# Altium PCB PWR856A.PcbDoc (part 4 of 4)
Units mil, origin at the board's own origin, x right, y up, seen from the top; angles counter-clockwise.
Board outline 4000 x 4000 mil, 8 copper layers (Top Layer, Signal Layer 1, Signal Layer 2, Signal Layer 3, Signal Layer 4, Signal Layer 5, Signal Layer 6, Bottom Layer), stack 60.4 mil thick; 246 components, 78 nets, 563 pads, 817 vias.
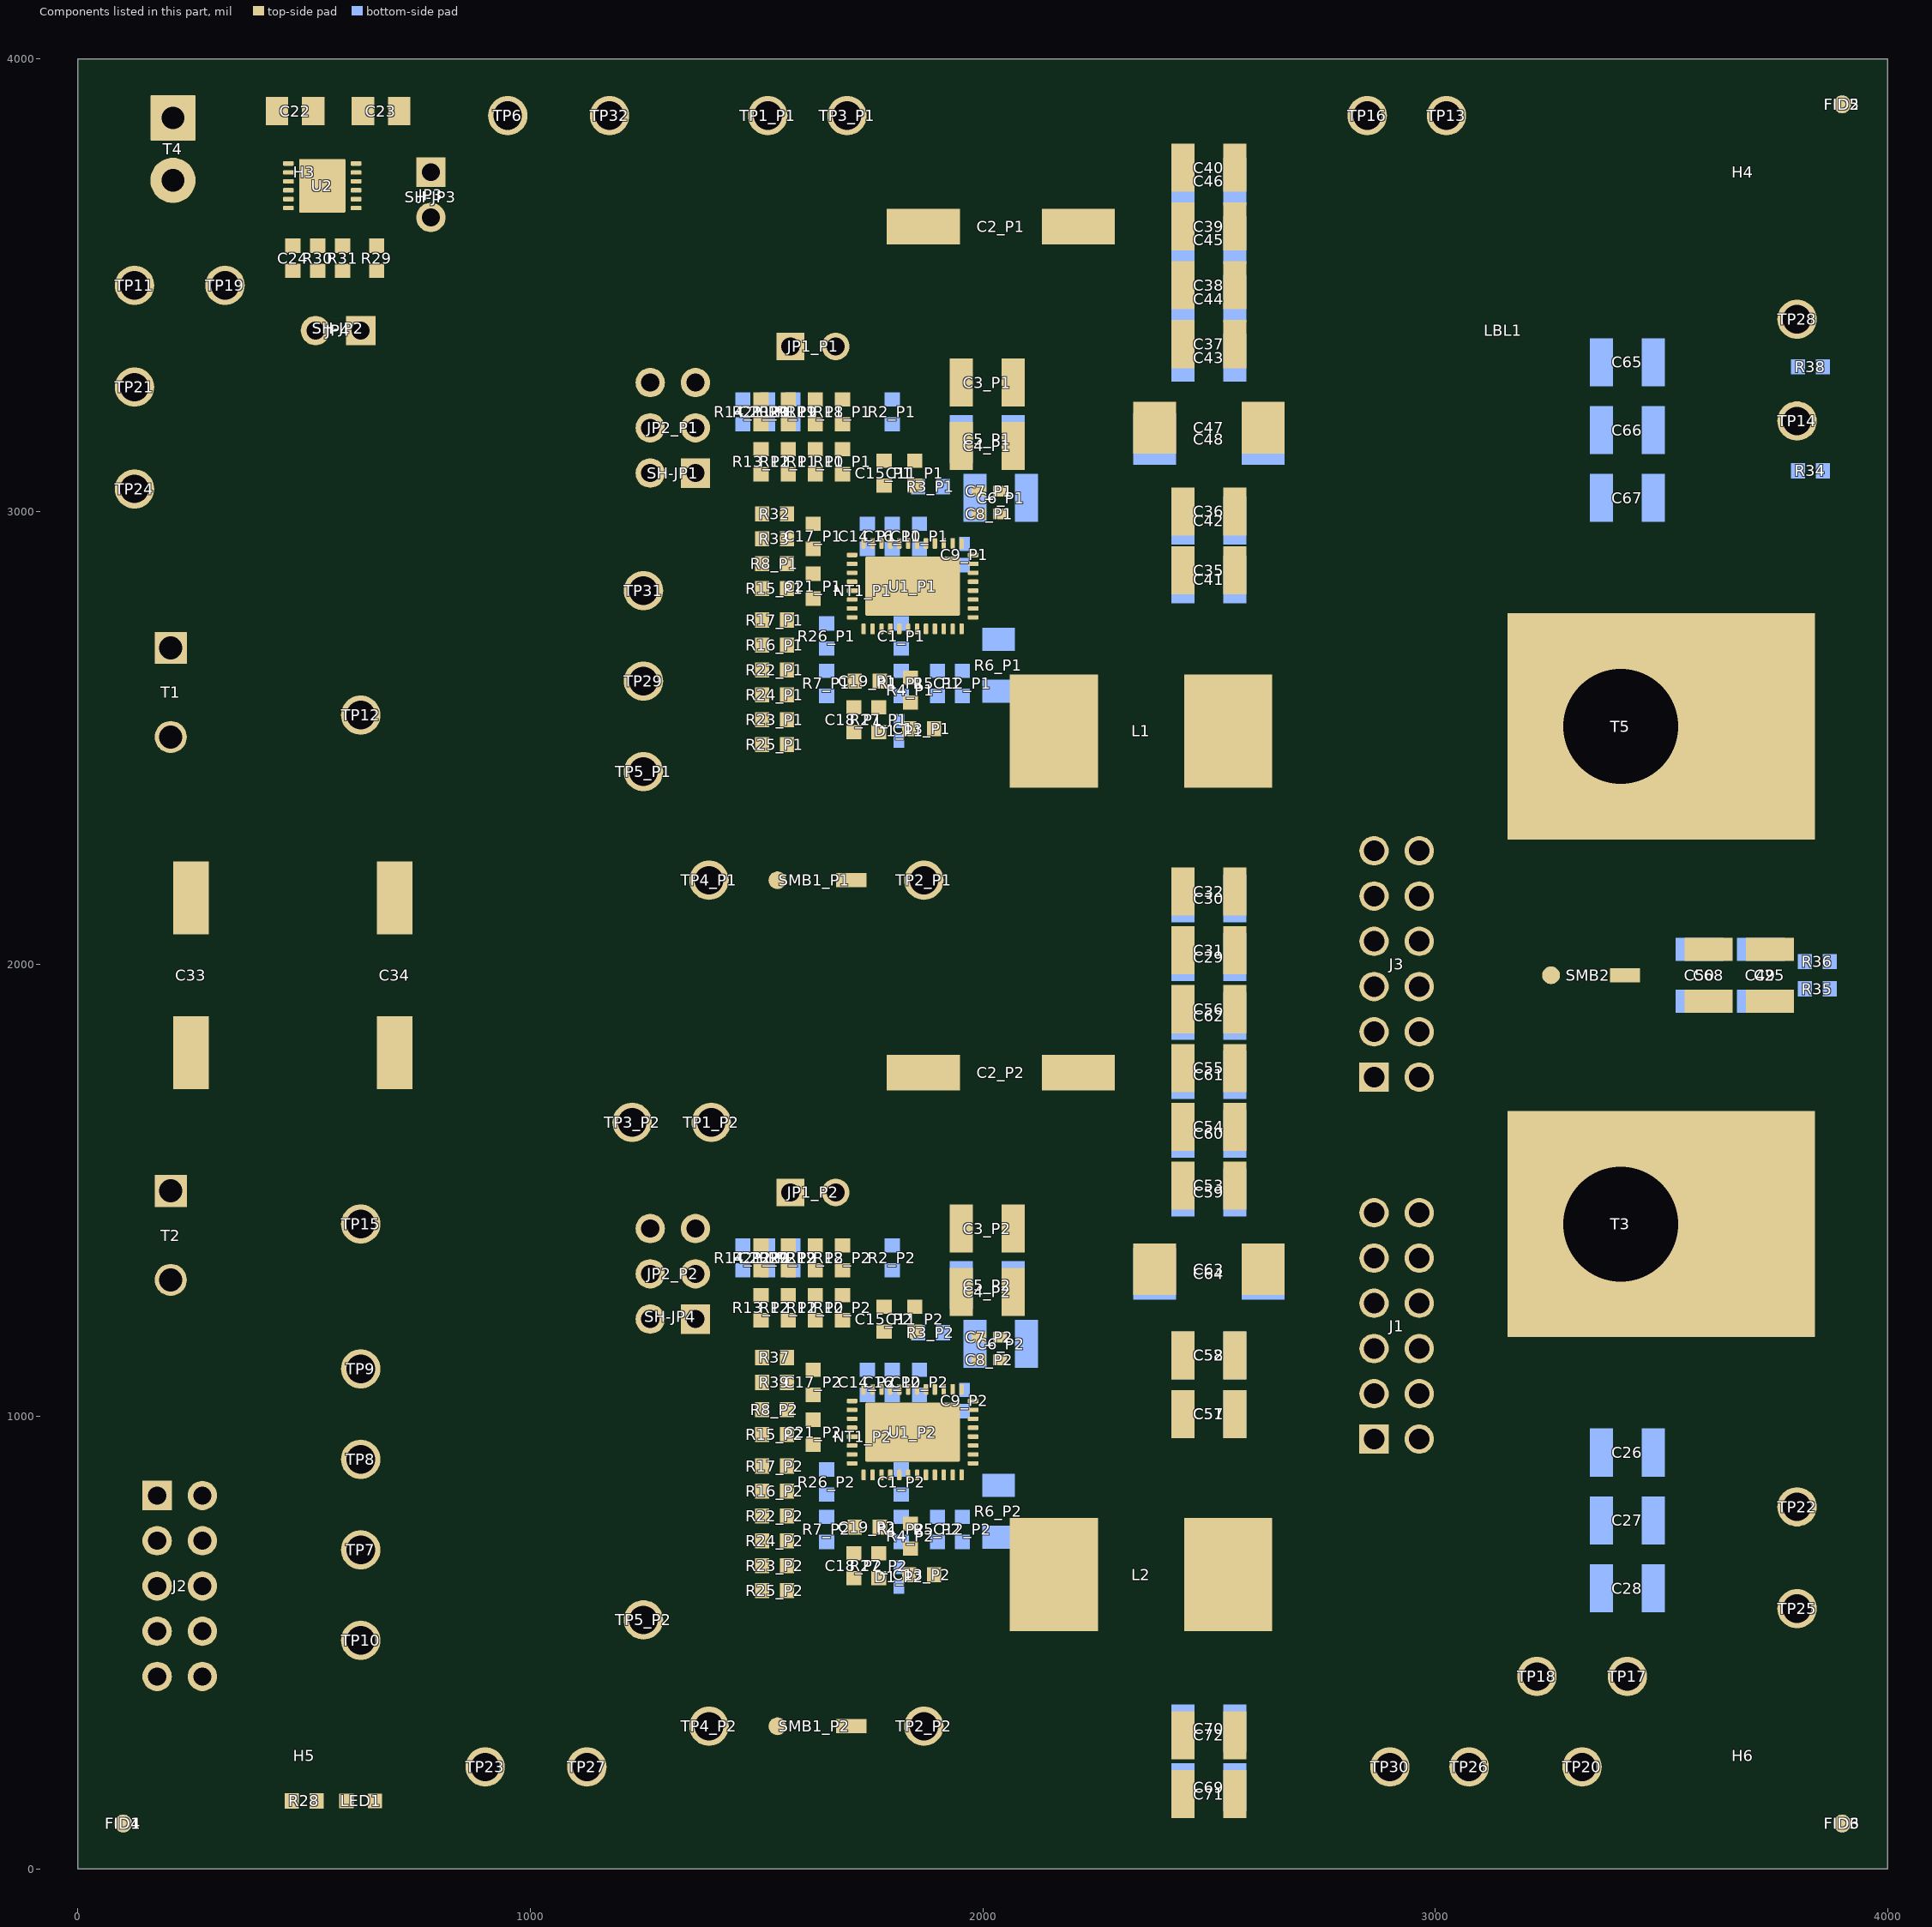
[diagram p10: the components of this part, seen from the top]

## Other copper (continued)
Signal Layer 3:
  pour cut-out: 1400,1705 cw(c1400,1650) 1455,1650 cw(c1400,1650) 1400,1595 cw(c1400,1650) 1345,1650 cw(c1400,1650)
  pour cut-out: 1225,1705 cw(c1225,1650) 1280,1650 cw(c1225,1650) 1225,1595 cw(c1225,1650) 1170,1650 cw(c1225,1650)
  pour cut-out: 1700,3930 cw(c1700,3875) 1755,3875 cw(c1700,3875) 1700,3820 cw(c1700,3875) 1645,3875 cw(c1700,3875)
  pour cut-out: 1525,3930 cw(c1525,3875) 1580,3875 cw(c1525,3875) 1525,3820 cw(c1525,3875) 1470,3875 cw(c1525,3875)
  pour cut-out: 2850,3930 cw(c2850,3875) 2905,3875 cw(c2850,3875) 2850,3820 cw(c2850,3875) 2795,3875 cw(c2850,3875)
  pour cut-out: 3025,3930 cw(c3025,3875) 3080,3875 cw(c3025,3875) 3025,3820 cw(c3025,3875) 2970,3875 cw(c3025,3875)
  pour cut-out: 3800,855 cw(c3800,800) 3855,800 cw(c3800,800) 3800,745 cw(c3800,800) 3745,800 cw(c3800,800)
  pour cut-out: 3800,630 cw(c3800,575) 3855,575 cw(c3800,575) 3800,520 cw(c3800,575) 3745,575 cw(c3800,575)
  pour cut-out: 3225,480 cw(c3225,425) 3280,425 cw(c3225,425) 3225,370 cw(c3225,425) 3170,425 cw(c3225,425)
  pour cut-out: 2900,280 cw(c2900,225) 2955,225 cw(c2900,225) 2900,170 cw(c2900,225) 2845,225 cw(c2900,225)
  pour cut-out: 3075,280 cw(c3075,225) 3130,225 cw(c3075,225) 3075,170 cw(c3075,225) 3020,225 cw(c3075,225)
  text ".Layer_Name" at 680,-670 h60
Signal Layer 5:
  pour cut-out: 2574.14,2840 cw(c2574.14,2874.14) 2550,2850 2508.54,2891.46 ccw(c2500,2882.93) 2500,2895 2497.07,2895 ccw(c2497.07,2877.93) 2485,2890 2465,2870 2445,2870 2445,2880 2495,2930 2495,3735 2560,3800 2910.86,3800 ccw(c2910.86,3834.14) 2935,3810 2944.96,3819.96 ccw(c2884.5,3880.42) 2970,3880.42 3023.99,3880.42 cw(c3023.99,3878.99) 3025,3880 3025,3820 ccw(c3025,3747.57) 2973.79,3798.79 2952.07,3777.07 cw(c2935,3794.14) 2935,3770 2584.14,3770 ccw(c2584.14,3735.86) 2560,3760 2527.07,3727.07 ccw(c2544.14,3710) 2520,3710 2520,2944.14 ccw(c2554.14,2944.14) 2530,2920 2572.93,2877.07 ccw(c2590,2894.14) 2590,2870 cw(c2590,2855) 2605,2855 cw(c2590,2855) 2590,2840
  pour cut-out: 3960,719.14 cw(c3925.86,719.14) 3950,695 3876.51,621.51 ccw(c3928.43,569.58) 3855,569.58 3801.01,569.58 cw(c3801.01,571.01) 3800,570 3800,630 ccw(c3800,690.36) 3842.68,647.68 3909.39,714.39 ccw(c3883.79,740) 3920,740 3920,1810 3765.61,1964.39 cw(c3791.21,1990) 3755,1990 3755,2005 3770.86,2005 cw(c3770.86,1970.86) 3795,1995 3952.93,1837.07 cw(c3935.86,1820) 3960,1820
  pour cut-out: 2590,1025 cw(c2590,1020) 2595,1020 2595,1000 cw(c2590,1000) 2590,995 2552.07,995 ccw(c2552.07,977.93) 2540,990 2528.54,978.54 ccw(c2537.07,970) 2525,970 2525,967.07 ccw(c2542.07,967.07) 2530,955 2537.93,947.07 ccw(c2555,964.14) 2555,940 2720.86,940 cw(c2720.86,905.86) 2745,930 3002.93,672.07 cw(c2985.86,655) 3010,655 3010,322.07 ccw(c3027.07,322.07) 3015,310 3070,255 3070,220 cw(c3068.99,221.01) 3068.99,219.58 3020,219.58 3020,233.79 ccw(c2968.79,233.79) 3005,270 2993.54,281.46 ccw(c2985,272.93) 2985,285 2970,285 2970,665 2725,910 2535,910 2485,960 2485,975 2455,1005 2455,1025 2485,1025 cw(c2485,1015) 2495,1015 2495,1010 ccw(c2505,1010) 2505,1000 ccw(c2505,1010) 2515,1010 2515,1015 cw(c2525,1015) 2525,1025
  pour cut-out: 3225,480 cw(c3225,425) 3280,425 cw(c3225,425) 3225,370 cw(c3225,425) 3170,425 cw(c3225,425)
  pour cut-out: 3075,280 cw(c3075,225) 3130,225 cw(c3075,225) 3075,170 cw(c3075,225) 3020,225 cw(c3075,225)
  pour cut-out: 3025,3930 cw(c3025,3875) 3080,3875 cw(c3025,3875) 3025,3820 cw(c3025,3875) 2970,3875 cw(c3025,3875)
  pour cut-out: 2850,3930 cw(c2850,3875) 2905,3875 cw(c2850,3875) 2850,3820 cw(c2850,3875) 2795,3875 cw(c2850,3875)
  pour cut-out: 1700,3930 cw(c1700,3875) 1755,3875 cw(c1700,3875) 1700,3820 cw(c1700,3875) 1645,3875 cw(c1700,3875)
  pour cut-out: 1525,3930 cw(c1525,3875) 1580,3875 cw(c1525,3875) 1525,3820 cw(c1525,3875) 1470,3875 cw(c1525,3875)
  pour cut-out: 3800,855 cw(c3800,800) 3855,800 cw(c3800,800) 3800,745 cw(c3800,800) 3745,800 cw(c3800,800)
  pour cut-out: 3800,630 cw(c3800,575) 3855,575 cw(c3800,575) 3800,520 cw(c3800,575) 3745,575 cw(c3800,575)
  pour cut-out: 1400,1705 cw(c1400,1650) 1455,1650 cw(c1400,1650) 1400,1595 cw(c1400,1650) 1345,1650 cw(c1400,1650)
  pour cut-out: 1225,1705 cw(c1225,1650) 1280,1650 cw(c1225,1650) 1225,1595 cw(c1225,1650) 1170,1650 cw(c1225,1650)
  pour cut-out: 2845,225 ccw(c2900,225) 2900,170 ccw(c2900,225) 2955,225 2955,245.86 cw(c2989.14,245.86) 2965,270 2982.93,287.93 ccw(c2965.86,305) 2990,305 2990,660.46 2730.46,920 2545.18,920 2510,955.18 2510,982 2467,1025 2410,1025 ccw(c2410,1020) 2405,1020 2405,1000 ccw(c2410,1000) 2410,995 2443.15,995 cw(c2443.15,959.15) 2468.5,984.5 cw(c2443.15,959.15) 2479,959.15 2479,949.49 ccw(c2499.49,949.49) 2485,935 2522.93,897.07 ccw(c2540,914.14) 2540,890 2707.93,890 cw(c2707.93,872.93) 2720,885 2952.93,652.07 cw(c2935.86,635) 2960,635 2960,312.07 cw(c2942.93,312.07) 2955,300 2942.07,287.07 cw(c2925,304.14) 2925,280 2900,280 ccw(c2900,225)
  pour cut-out: 2410,2870 2410,2835 2430,2835 2505,2910 2505,3730 2565,3790 2790,3790 2825,3825 2865,3825 2895,3855 2895,3890 2865,3920 2830,3920 2800,3890 2800,3845 2775,3820 2550,3820 2474,3744 2474,3709 2474,2924 2420,2870
  pour cut-out: 2005,1025 2025,1025 2070,1070 2070,1900 2020,1950 1635,1950 1420,1735 1350,1735 1275,1660 1275,1635 1290,1635 1360,1705 1435,1705 1650,1920 2000,1920 2040,1880 2040,1095 2005,1060
  pour cut-out: 2005,2895 2025,2895 2070,2940 2070,3765 1945,3890 1730,3890 1730,3860 1935,3860 2040,3755 2040,2965 2005,2930
  text ".Layer_Name" at 680,-670 h60
Signal Layer 1:
  pour cut-out: 3025,3930 cw(c3025,3875) 3080,3875 cw(c3025,3875) 3025,3820 cw(c3025,3875) 2970,3875 cw(c3025,3875)
  pour cut-out: 2850,3930 cw(c2850,3875) 2905,3875 cw(c2850,3875) 2850,3820 cw(c2850,3875) 2795,3875 cw(c2850,3875)
  pour cut-out: 1700,3930 cw(c1700,3875) 1755,3875 cw(c1700,3875) 1700,3820 cw(c1700,3875) 1645,3875 cw(c1700,3875)
  pour cut-out: 1525,3930 cw(c1525,3875) 1580,3875 cw(c1525,3875) 1525,3820 cw(c1525,3875) 1470,3875 cw(c1525,3875)
  pour cut-out: 1400,1705 cw(c1400,1650) 1455,1650 cw(c1400,1650) 1400,1595 cw(c1400,1650) 1345,1650 cw(c1400,1650)
  pour cut-out: 1225,1705 cw(c1225,1650) 1280,1650 cw(c1225,1650) 1225,1595 cw(c1225,1650) 1170,1650 cw(c1225,1650)
  pour cut-out: 3800,855 cw(c3800,800) 3855,800 cw(c3800,800) 3800,745 cw(c3800,800) 3745,800 cw(c3800,800)
  pour cut-out: 3800,630 cw(c3800,575) 3855,575 cw(c3800,575) 3800,520 cw(c3800,575) 3745,575 cw(c3800,575)
  pour cut-out: 3225,480 cw(c3225,425) 3280,425 cw(c3225,425) 3225,370 cw(c3225,425) 3170,425 cw(c3225,425)
  pour cut-out: 3075,280 cw(c3075,225) 3130,225 cw(c3075,225) 3075,170 cw(c3075,225) 3020,225 cw(c3075,225)
  pour cut-out: 2900,280 cw(c2900,225) 2955,225 cw(c2900,225) 2900,170 cw(c2900,225) 2845,225 cw(c2900,225)
  text ".Layer_Name" at 680,-670 h60
Signal Layer 6:
  pour cut-out: 3025,3930 cw(c3025,3875) 3080,3875 cw(c3025,3875) 3025,3820 cw(c3025,3875) 2970,3875 cw(c3025,3875)
  pour cut-out: 2850,3930 cw(c2850,3875) 2905,3875 cw(c2850,3875) 2850,3820 cw(c2850,3875) 2795,3875 cw(c2850,3875)
  pour cut-out: 1700,3930 cw(c1700,3875) 1755,3875 cw(c1700,3875) 1700,3820 cw(c1700,3875) 1645,3875 cw(c1700,3875)
  pour cut-out: 1525,3930 cw(c1525,3875) 1580,3875 cw(c1525,3875) 1525,3820 cw(c1525,3875) 1470,3875 cw(c1525,3875)
  pour cut-out: 1400,1705 cw(c1400,1650) 1455,1650 cw(c1400,1650) 1400,1595 cw(c1400,1650) 1345,1650 cw(c1400,1650)
  pour cut-out: 1225,1705 cw(c1225,1650) 1280,1650 cw(c1225,1650) 1225,1595 cw(c1225,1650) 1170,1650 cw(c1225,1650)
  pour cut-out: 3800,855 cw(c3800,800) 3855,800 cw(c3800,800) 3800,745 cw(c3800,800) 3745,800 cw(c3800,800)
  pour cut-out: 3800,630 cw(c3800,575) 3855,575 cw(c3800,575) 3800,520 cw(c3800,575) 3745,575 cw(c3800,575)
  pour cut-out: 3225,480 cw(c3225,425) 3280,425 cw(c3225,425) 3225,370 cw(c3225,425) 3170,425 cw(c3225,425)
  pour cut-out: 2900,280 cw(c2900,225) 2955,225 cw(c2900,225) 2900,170 cw(c2900,225) 2845,225 cw(c2900,225)
  pour cut-out: 3075,280 cw(c3075,225) 3130,225 cw(c3075,225) 3075,170 cw(c3075,225) 3020,225 cw(c3075,225)
  text ".Layer_Name" at 680,-670 h60
Bottom Layer:
  pour cut-out: 3025,3820 ccw(c3025,3875) 3080,3875 ccw(c3025,3875) 3025,3930 ccw(c3025,3875) 2970,3875 ccw(c3025,3875)
  pour cut-out: 2850,3820 ccw(c2850,3875) 2905,3875 ccw(c2850,3875) 2850,3930 ccw(c2850,3875) 2795,3875 ccw(c2850,3875)
  pour cut-out: 1700,3820 ccw(c1700,3875) 1755,3875 ccw(c1700,3875) 1700,3930 ccw(c1700,3875) 1645,3875 ccw(c1700,3875)
  pour cut-out: 1525,3820 ccw(c1525,3875) 1580,3875 ccw(c1525,3875) 1525,3930 ccw(c1525,3875) 1470,3875 ccw(c1525,3875)
  pour cut-out: 1225,1595 ccw(c1225,1650) 1280,1650 ccw(c1225,1650) 1225,1705 ccw(c1225,1650) 1170,1650 ccw(c1225,1650)
  pour cut-out: 1400,1595 ccw(c1400,1650) 1455,1650 ccw(c1400,1650) 1400,1705 ccw(c1400,1650) 1345,1650 ccw(c1400,1650)
  pour cut-out: 3075,170 ccw(c3075,225) 3130,225 ccw(c3075,225) 3075,280 ccw(c3075,225) 3020,225 ccw(c3075,225)
  pour cut-out: 3800,745 ccw(c3800,800) 3855,800 ccw(c3800,800) 3800,855 ccw(c3800,800) 3745,800 ccw(c3800,800)
  pour cut-out: 3225,370 ccw(c3225,425) 3280,425 ccw(c3225,425) 3225,480 ccw(c3225,425) 3170,425 ccw(c3225,425)
  pour cut-out: 3800,520 ccw(c3800,575) 3855,575 ccw(c3800,575) 3800,630 ccw(c3800,575) 3745,575 ccw(c3800,575)
  pour cut-out: 2900,170 ccw(c2900,225) 2955,225 ccw(c2900,225) 2900,280 ccw(c2900,225) 2845,225 ccw(c2900,225)
  text ".Layer_Name" at 680,-670 h60

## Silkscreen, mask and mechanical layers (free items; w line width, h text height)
Top Overlay:
  lines w10: 805,3800 805,3810 ; 919.52,2962 1119.52,2962 1129.52,2972 1129.52,3372 1159.52,3402 1179.52,3422 1409.52,3422 1459.52,3372 1459.52,3182 1479.52,3162 ; 920,1090 1120,1090 1130,1100 1130,1500 1160,1530 1180,1550 1410,1550 1460,1500 1460,1310 1480,1290
  text "GND_P1" at 2630,3880 h25
  text "VOUT_P1" at 3110,3880 h25
  text "AUX_5V" at 880,3760 h25
  text "GND" at 1140,3760 h25
  text "PVIN_P1" at 1440,3760 h25
  text "GND_P1" at 1630,3760 h25
  text "EXT_5.1V" at 1620,3440 h25
  text "GND" at 90,3390 h25
  text "Ext_AVIN" at 240,3390 h25
  text "Remote SNS-" at 3940,3360 h25 r90
  text "AVIN - PVIN" at 440,3280 h25
  text "VSHARE" at 210,3200 h25
  text "'.PRJ_Number'  Rev. '.PCB_Rev'" at 2840,3200 h80
  text "CNTL_SEL1" at 1180,3040 h25 r90
  text "GND" at 210,2990 h25
  text "MSEL1" at 940,2980 h25 r90
  text "ADRSEL" at 995,2980 h25 r90
  text "VSEL" at 1050,2980 h25 r90
  text "MSEL2" at 1105,2980 h25 r90
  text "Remote SNS+" at 3940,2980 h25 r90
  text "BC_CLK" at 1010,2820 h25
  text "BC_DAT" at 1010,2610 h25
  text "PVIN" at 480,2540 h40 r90
  text "GND" at 3100,2500 h40 r90
  text "PVIN" at 575,2425 h25
  text "PG_U1" at 1020,2420 h25
  text "GND" at 1260,2110 h25
  text "SW_P1" at 1950,2110 h25
  text "PVIN_P2" at 970,1650 h25
  text "GND_P2" at 1490,1650 h25
  text "EXT_5.1V" at 1650,1570 h25
  text "VOUT" at 3100,1380 h40 r90
  text "GND" at 480,1340 h40 r90
  text "GND" at 575,1300 h25
  text "CNTL_SEL2" at 1185,1170 h25 r90
  text "MSEL1" at 940,1110 h25 r90
  text "ADRSEL" at 995,1110 h25 r90
  text "VSEL" at 1050,1110 h25 r90
  text "MSEL2" at 1105,1110 h25 r90
  text "CNTL" at 740,1020 h25
  text "SMBALRT" at 740,820 h25
  text "VOUT" at 3600,780 h30
  text "DATA" at 740,620 h25
  text "GND" at 3610,560 h30
  text "PG_U2" at 1020,550 h25
  text "CH_A" at 3510,460 h30
  text "CH_B" at 3020,450 h30
  text "CLK" at 740,420 h25
  text "PMBus Conn." at 475,305 h30 r90
  text "SW_P2" at 1850,195 h25
  text "GND" at 1350,190 h25
  text "GND" at 3420,180 h25
  text "GND" at 740,160 h25
  text "SYNC" at 1200,160 h25
  text "GND_P2" at 2790,100 h25
  text "VOUT_P2" at 3000,100 h25
  text ".Layer_Name" at 610,-670 h60
Bottom Overlay:
  text ".Layer_Name" at 680,-670 h60
Top Paste:
  text ".Layer_Name" at 700,-700 h60
Bottom Paste:
  text ".Layer_Name" at 700,-700 h60
Top Solder:
  region: 1975,2710 cw(c1975,2695) 1990,2695 cw(c1975,2695) 1975,2680 cw(c1975,2695) 1960,2695 cw(c1975,2695)
  region: 2046.5,2802.28 cw(c2046.5,2787.28) 2061.5,2787.28 cw(c2046.5,2787.28) 2046.5,2772.28 cw(c2046.5,2787.28) 2031.5,2787.28 cw(c2046.5,2787.28)
  region: 2046.5,2932.28 cw(c2046.5,2917.28) 2061.5,2917.28 cw(c2046.5,2917.28) 2046.5,2902.28 cw(c2046.5,2917.28) 2031.5,2917.28 cw(c2046.5,2917.28)
  region: 1909.26,2986.14 cw(c1909.26,2971.14) 1924.26,2971.14 cw(c1909.26,2971.14) 1909.26,2956.14 cw(c1909.26,2971.14) 1894.26,2971.14 cw(c1909.26,2971.14)
  region: 1909.26,1116.14 cw(c1909.26,1101.14) 1924.26,1101.14 cw(c1909.26,1101.14) 1909.26,1086.14 cw(c1909.26,1101.14) 1894.26,1101.14 cw(c1909.26,1101.14)
  region: 2046.5,1062.28 cw(c2046.5,1047.28) 2061.5,1047.28 cw(c2046.5,1047.28) 2046.5,1032.28 cw(c2046.5,1047.28) 2031.5,1047.28 cw(c2046.5,1047.28)
  region: 2046.5,932.28 cw(c2046.5,917.28) 2061.5,917.28 cw(c2046.5,917.28) 2046.5,902.28 cw(c2046.5,917.28) 2031.5,917.28 cw(c2046.5,917.28)
  region: 1975,840 cw(c1975,825) 1990,825 cw(c1975,825) 1975,810 cw(c1975,825) 1960,825 cw(c1975,825)
  text ".Layer_Name" at 800,-700 h60
Bottom Solder:
  text ".Layer_Name" at 700,-700 h60
Drill Guide:
  text ".Layer_Name" at 700,-700 h60
M1 Board Outline:
  the board outline again, w10
  text ".Layer_Name" at 577,-1558.49 h60
M2 Board Dimensions:
  rectangle: 0,-975 125,-850
  rectangle: 125,-1100 500,-975
  lines w7: 0,-975 1000,-975 ; 0,-850 0,-1100 1000,-1100 1000,-850 ; 125,-1100 125,-850 ; 250,-1100 250,-850 ; 500,-1100 500,-850 ; 750,-1100 750,-850
  lines w10: 0,-850 1000,-850
  text ".Layer_Name" at 577,-1558.49 h60
M3 3D STEP Top:
  text ".Layer_Name" at 577,-1558.49 h60
M4 3D STEP Bottom:
  text ".Layer_Name" at 577,-1558.49 h60
M5 Assembly Top:
  lines w10: -298.5,-1837.5 1277,-1837.5 ; -292,-1630.17 6308,-1630.17 ; -292,-1426.83 6310,-1426.83 ; -292,-1223.5 -292,-1833.5 3713,-1833.5 6310,-1833.5 6310,-1223.5 -291.5,-1223.5 -291.5,-1833.5 ; 2173,-1833.5 2173,-1223.5 ; 3440,-1426.83 3440,-1223.5 ; 4280,-1426.83 4280,-1223.5 ; 4902,-1840 4902,-1637.17
  text "COMPONENTS MARKED 'DNP' SHOULD NOT BE POPULATED." at 1153.5,-1018.5 h60
  text "ASSEMBLY VARIANT:" at 1153,-1134 h60
  text ".VariantName" at 2189,-1134 h60
  text "BOARD #:" at 2248,-1355.67 h60
  text ".PRJ_Number" at 2793.5,-1355.67 h60
  text "REV:" at 3638,-1355.67 h60
  text ".PCB_Rev" at 3929.5,-1355.67 h60
  text "SVN REV:" at 4476,-1355.67 h60
  text ".VersionControl_RevNumber" at 4982,-1355.67 h60
  text "PCB VIEWED FROM TOP SIDE" at -235.5,-1359.67 h60
  text "TID #:" at 2248,-1559 h60
  text ".TID" at 2793.5,-1559 h60
  text ".plot_File_Name" at 577,-1764.34 h60
  text "GENERATED    :" at 2250,-1764.34 h60
  text ".Print_Date" at 3119.5,-1764.34 h60
  text ".Print_Time" at 3848.5,-1764.34 h60
  text "TEXAS INSTRUMENTS" at 5113,-1764.34 h60
  text "PLOT NAME =" at -235.5,-1768.34 h60
M6 Assembly Bottom:
  lines w10: -292.5,-1427.33 6309.5,-1427.33 ; -290.5,-1630.67 6309.5,-1630.67 ; 1106.5,-1834.5 1106.5,-1631.67 ; 1737.5,-1427.33 1737.5,-1224 ; 2577.5,-1427.33 2577.5,-1224 ; 3844.5,-1834 3844.5,-1224 ; 4733.5,-1834 6309,-1834 6309,-1224 -292.5,-1224 -292.5,-1834 2304.5,-1834 6309.5,-1834 6309.5,-1224
  text "COMPONENTS MARKED 'DNP' SHOULD NOT BE POPULATED." at 6102,-1018 h60
  text ".VariantName" at 5058,-1134 h60
  text "ASSEMBLY VARIANT:" at 6097,-1134 h60
  text ".VersionControl_RevNumber" at 1026.5,-1350.17 h60
  text "SVN REV:" at 1541.5,-1356.17 h60
  text ".PCB_Rev" at 2088,-1356.17 h60
  text "REV:" at 2379.5,-1356.17 h60
  text ".PRJ_Number" at 3224,-1356.17 h60
  text "BOARD #:" at 3769.5,-1356.17 h60
  text "PCB VIEWED FROM BOTTOM SIDE" at 6246,-1356.17 h60
  text ".TID" at 3224,-1559.5 h60
  text "TID #:" at 3769.5,-1559.5 h60
  text "TEXAS INSTRUMENTS" at 895.5,-1758.84 h60
  text ".Print_Time" at 2169,-1764.84 h60
  text ".Print_Date" at 2898,-1764.84 h60
  text "GENERATED    :" at 3767.5,-1764.84 h60
  text ".plot_File_Name" at 5440.5,-1764.84 h60
  text "PLOT NAME =" at 6246,-1764.84 h60
M9 Title Sheet:
  drawing of 58 lines, arcs and shapes, not listed
  text "1" at 739.84,7336.5 h70
  text "2" at 3235.5,7336.5 h70
  text "3" at 5724.84,7336.5 h70
  text "4" at 8231.51,7336.5 h70
  text "5" at 10730.5,7336.5 h70
  text "6" at 13235.5,7336.5 h70
  text "A" at -416.5,6193.5 h70
  text "A" at 14383.5,6193.5 h70
  text "B" at -416.5,3813.5 h70
  text "B" at 14383.5,3813.5 h70
  text "1" at 1443.23,2273.96 h70 r270
  text "C" at -416.5,1438.5 h70
  text "C" at 14383.5,1438.5 h70
  text "PROJECT TITLE:" at 11343.5,-422.5 h45
  text "'.PRJ_Title'" at 11393.5,-555.83 h70
  text "DESIGNED FOR:" at 11343.5,-723.5 h45
  text "'.PRJ_Customer'" at 11393.5,-863.5 h70
  text "D" at -416.5,-931.5 h70
  text "D" at 14383.5,-931.5 h70
  text "FILE NAME:" at 11343.5,-1023.5 h45
  text ".PCB_File_Name_No_Path" at 11393.5,-1143.5 h70
  text "Texas Instruments (TI) and/or its licensors do not warrant the accuracy or completeness of this specification" at 6374,-1305.34 h45
  text "ENGINEER:" at 11343.5,-1313.5 h45
  text "LAYOUT BY:" at 12848.5,-1313.5 h45
  text "or any information contained therein. TI and/or its licensors do not warrant that this design will meet" at 6329.01,-1418 h45
  text ".PRJ_Engineer" at 11393.5,-1468.49 h70
  text ".PCB_Layout" at 12899,-1468.49 h70
  text "the specifications, will be suitable for your application or fit for any particular purpose, or will operate in" at 6329.01,-1530.67 h45
  text ".Layer_Name" at 577,-1558.49 h60
  text "ALTIUM DESIGNER VERSION:" at 12848.5,-1623.5 h45
  text "an implementation. TI and/or its licensors do not warrant that the design is production worthy. You should" at 6329.01,-1643.33 h45
  text "completely validate and test your design implementation to confirm the system functionality for your application." at 6374,-1756 h45
  text ".print_Scale" at 11393.5,-1756.83 h70
  text ".Application_BuildNumber" at 12899,-1756.83 h70
  text "2" at 3235.5,-1963.5 h70
  text "3" at 5724.84,-1963.5 h70
  text "4" at 8231.51,-1963.5 h70
  text "5" at 10730.5,-1963.5 h70
  text "6" at 13235.5,-1963.5 h70
M10 Fab Notes:
  drawing of 216 lines, arcs and shapes, not listed
  text "DESIGN INFORMATION" at 12357.02,6157 h60
  text "(REFER ALSO ARRAY/PANEL PROFILING INFORMATION)" at 11995.46,5995.29 h60
  text "BOARD SIZE" at 11309.46,5991 h60
  text "4000MIL" at 11771.78,5863.18 h60
  text "X" at 12277.46,5863.18 h60
  text "4000MIL" at 12508.78,5863.18 h60
  text "Number of Layers :" at 11712.46,5666 h60
  text "8" at 12807.27,5656 h60
  text "MIN. TRACK WIDTH:" at 11712.46,5527 h60
  text "8" at 12808.7,5527 h60
  text "MIL" at 12963.46,5527 h60
  text "8" at 12806,5412 h60
  text "MIN. CLEARANCE:" at 11712.46,5395 h60
  text "MIL" at 12963.46,5395 h60
  text "MIN. VIA PAD SIZE:" at 11712.46,5263 h60
  text "22" at 12778.71,5263 h60
  text "MIL" at 12963.46,5263 h60
  text "0.05mm (2MIL)" at 12407.46,5121.29 h60
  text "MINIMUM ANNULAR RING" at 11383.23,5117 h60
  text "EXTERNAL" at 13115.46,5117 h60
  text "PER" at 11583.23,4999 h60
  text "IPC-D-275 CLASS 2 LEVEL C" at 11803.23,4999 h60
  text "MIL, HOLES" at 13291.46,4886.71 h60
  text "+/-" at 12899,4886 h60
  text "+/-" at 13753,4886 h60
  text "REGISTRATION TOLERANCES:" at 11383.23,4881 h60
  text "METAL" at 12583,4881 h60
  text "5" at 13159.2,4881 h60
  text "3" at 13992.2,4881 h60
  text "MIL" at 14108.46,4881 h60
  text "MATERIAL:" at 11308.46,4671.54 h60
  text "FR-4 High Tg" at 12294.9,4531.21 h60
  text "FR-408" at 11729.46,4522.64 h60
  text "X" at 12141.46,4522.64 h60
  text "OTHER" at 13217.46,4522.64 h60
  text "62 MIL (1.6mm) +/-10%" at 12049.56,4359.92 h60
  text "THICKNESS:" at 11383.23,4355.64 h60
  text "X" at 11921.4,4355.64 h60
  text "OTHER" at 13334.46,4355.64 h60
  text "TOLERANCE:" at 11383.23,4197.64 h60
  text "X" at 12222.53,4197.64 h60
  text "ANSI IPC-6012 TYPE 3 CLASS 2" at 12409.48,4197.64 h60
  text "OTHER +/-" at 12409.46,4041.64 h60
  text "BOW & TWIST:" at 11383.23,3884.64 h60
  text "X" at 12222.53,3884.64 h60
  text "ANSI IPC-6012 TYPE 3 CLASS 2" at 12409.48,3884.64 h60
  text "OTHER +/-" at 12409.46,3726.13 h60
  text "COPPER THICKNESS (FINISHED):" at 11308.46,3590.64 h60
  text "1.4MIL (1oz)" at 12188.46,3437.92 h60
  text "2MIL (1.4oz)" at 12955.46,3437.92 h60
  text "2.8MIL (2oz)" at 13682.46,3437.92 h60
  text "OUTER:" at 11665.46,3433.64 h60
  text "X" at 13576,3432 h60
  text "X" at 12831,3287 h60
  text "1.4MIL (1oz)" at 12188.46,3280.92 h60
  text "2.8MIL (2oz)" at 12955.46,3280.92 h60
  text "N/A" at 13682,3281.29 h60
  text "INNER SIGNAL:" at 11376.38,3276.64 h60
  text "DRILLING:" at 11308.46,3137.64 h60
  text "REFERENCE:" at 11383.23,3020.64 h60
  text "X" at 12031.46,3020.64 h60
  text "AS SHOWN" at 12218.46,3020.64 h60
  text "X" at 12932.46,3020.64 h60
  text "NC_DRILL FILES" at 13069.46,3020.64 h60
  text "1.9MIL" at 13701.92,2884.28 h60
  text "PTH MIN COPPER THICKNESS:" at 11383.23,2862.64 h60
  text "1MIL" at 12870.46,2862.64 h60
  text "OTHER" at 13367.46,2862.64 h60
  text "X" at 13259.46,2857.64 h60
  text "BOARD FINISH:" at 11308.46,2703.64 h60
  text "SILKSCREEN:" at 11463.68,2585.64 h60
  text "X" at 12412.46,2585.64 h60
  text "TOP" at 12538.46,2585.64 h60
  text "X" at 12922.46,2585.64 h60
  text "BOTTOM" at 13049.46,2585.64 h60
  text "SILKSCREEN COLOR:" at 11463.68,2418.64 h60
  text "X" at 12411.42,2418.64 h60
  text "WHITE" at 12538.46,2418.64 h60
  text "OTHER" at 13049.46,2418.64 h60
  text "SOLDER RESIST COLOR:" at 11463.68,2248.64 h60
  text "X" at 12120,2095 h60
  text "X" at 12645,2095 h60
  text "GREEN" at 11658.46,2089.44 h60
  text "BLUE" at 12249.46,2089.44 h60
  text "MATTE" at 12774.46,2089.44 h60
  text "OTHER" at 13287.46,2089.44 h60
  text "IMMERSION GOLD (ENIG)" at 12369.46,1900.92 h60
  text "X" at 12185,1900 h60
  text "ENEPIG" at 13707,1897.64 h60
  text "SURFACE FINISH:" at 11308.46,1896.64 h60
  text "IMM. TIN/SILVER OR EQUIV" at 11638,1739.64 h60
  text "OTHER" at 13069.46,1739.64 h60
  text "ARRAY/PANEL:" at 11308.46,1560.64 h60
  text "CUT AND TRIM PER MECH LAYER 1" at 12369.46,1556.35 h60
  text "N.C. ROUTE" at 12369.46,1404.64 h60
  text "X" at 13048.46,1404.64 h60
  text "V. SCORE" at 13235.46,1404.64 h60
  text "CERTIFICATION:" at 11308.46,1267.64 h60
  text "MATERIALS AND WORKMANSHIP FOR ALL PCBS" at 12033.46,1267.64 h60
  text "TO MEET OR EXCEED THE REQUIREMENTS OF:" at 12033.46,1169.64 h60
  text "X" at 11659.96,1033.13 h60
  text "ANSI IPC-A-600F CLASS ->" at 11798.96,1033.13 h60
  text "X" at 13438.02,1033.13 h60
  text "2" at 13556.96,1033.14 h60
  text "1" at 13241.96,1031.64 h60
  text "3" at 13910.96,1031.64 h60
  text "X" at 11662.02,873.64 h60
  text "UL 94V-0" at 11798.96,873.64 h60
  text "X" at 12474.02,873.64 h60
  text "RoHS" at 12610.96,873.64 h60
  text "OTHER" at 13255.36,873.64 h60
  text "PER ORDER" at 13652.42,873.64 h60
  text "ADDITIONAL REQUIREMENTS:" at 11308.46,732.64 h60
  text "MICROSECTION:" at 11383.23,617.64 h60
  text "YES" at 12288.96,617.64 h60
  text "REQUIRED" at 13150.46,461.49 h60
  text "BARE BOARD ELEC. TEST:" at 11383.23,458.64 h60
  text "NONE" at 12688.96,458.64 h60
  text "X" at 13023.46,458.64 h60
  text "PER ORDER" at 13742.46,458.64 h60
  text "MANUFACTURER'S UL:" at 11383.23,301.64 h60
  text "RAIL" at 12548.96,297.35 h60
  text "METAL" at 13040.77,297.35 h60
  text "X" at 13416,297 h60
  text "SILK" at 13552.46,297.35 h60
  text ".Layer_Name" at 577,-1558.49 h60
M11 Gerber Information:
  lines w10: -300.5,-1827.5 1275,-1827.5 ; -292,-1630.17 6308,-1630.17 ; -292,-1426.83 6310,-1426.83 ; -292,-1223.5 -292,-1833.5 3713,-1833.5 6310,-1833.5 6310,-1223.5 -291.5,-1223.5 -291.5,-1833.5 ; 2173,-1833.5 2173,-1223.5 ; 3440,-1426.83 3440,-1223.5 ; 4280,-1426.83 4280,-1223.5 ; 4902,-1840 4902,-1637.17
  text "ALL ARTWORK VIEWED FROM TOP SIDE" at -228.5,-1355.67 h60
  text "BOARD #:" at 2248,-1355.67 h60
  text ".PRJ_Number" at 2793.5,-1355.67 h60
  text "REV:" at 3638,-1355.67 h60
  text ".PCB_Rev" at 3929.5,-1355.67 h60
  text "SVN REV:" at 4476,-1355.67 h60
  text ".VersionControl_RevNumber" at 4982,-1355.67 h60
  text "LAYER NAME =" at -237.5,-1552.49 h60
  text "TID #:" at 2248,-1559 h60
  text ".TID" at 2793.5,-1559 h60
  text "PLOT NAME =" at -237.5,-1758.34 h60
  text ".plot_File_Name" at 577,-1764.34 h60
  text "GENERATED    :" at 2250,-1764.34 h60
  text ".Print_Date" at 3119.5,-1764.34 h60
  text ".Print_Time" at 3848.5,-1764.34 h60
  text "TEXAS INSTRUMENTS" at 5113,-1764.34 h60
M12 Stackup:
  drawing of 503 lines, arcs and shapes, not listed
  text "Layer" at 6575.5,6792.8 h60
  text "Name" at 6985.41,6792.8 h60
  text "Material" at 7925.15,6792.8 h60
  text "Thickness" at 8784.92,6792.8 h60
  text "Constant" at 9434.76,6792.8 h60
  text "Board Layer Stack" at 10004.62,6792.8 h60
  text "1" at 6575.5,6672.8 h60
  text "Top Overlay" at 6985.41,6672.8 h60
  text "2" at 6575.5,6552.8 h60
  text "Top Solder" at 6985.41,6552.8 h60
  text "Solder Resist" at 7925.15,6552.8 h60
  text "0.50mil" at 8784.92,6552.8 h60
  text "3.3" at 9434.76,6552.8 h60
  text "3" at 6575.5,6432.8 h60
  text "Top Layer" at 6985.41,6432.8 h60
  text "Copper" at 7925.15,6432.8 h60
  text "2.80mil" at 8784.92,6432.8 h60
  text "4" at 6575.5,6312.8 h60
  text "Dielectric 1" at 6985.41,6312.8 h60
  text "FR-4 High TG" at 7925.15,6312.8 h60
  text "5.00mil" at 8784.92,6312.8 h60
  text "4.2" at 9434.76,6312.8 h60
  text "5" at 6575.5,6192.8 h60
  text "Signal Layer 1" at 6985.41,6192.8 h60
  text "Copper" at 7925.15,6192.8 h60
  text "2.80mil" at 8784.92,6192.8 h60
  text "6" at 6575.5,6072.8 h60
  text "Dielectric 2" at 6985.41,6072.8 h60
  text "FR-4 High TG" at 7925.15,6072.8 h60
  text "6.00mil" at 8784.92,6072.8 h60
  text "4.2" at 9434.76,6072.8 h60
  text "7" at 6575.5,5952.8 h60
  text "Signal Layer 2" at 6985.41,5952.8 h60
  text "Copper" at 7925.15,5952.8 h60
  text "2.80mil" at 8784.92,5952.8 h60
  text "8" at 6575.5,5832.8 h60
  text "Dielectric 3" at 6985.41,5832.8 h60
  text "FR-4 High TG" at 7925.15,5832.8 h60
  text "5.00mil" at 8784.92,5832.8 h60
  text "4.2" at 9434.76,5832.8 h60
  text "9" at 6575.5,5712.8 h60
  text "Signal Layer 3" at 6985.41,5712.8 h60
  text "Copper" at 7925.15,5712.8 h60
  text "2.80mil" at 8784.92,5712.8 h60
  text "10" at 6575.5,5592.8 h60
  text "Dielectric 5" at 6985.41,5592.8 h60
  text "FR-4 High TG" at 7925.15,5592.8 h60
  text "6.00mil" at 8784.92,5592.8 h60
  text "4.2" at 9434.76,5592.8 h60
  text "11" at 6575.5,5472.8 h60
  text "Signal Layer 4" at 6985.41,5472.8 h60
  text "Copper" at 7925.15,5472.8 h60
  text "2.80mil" at 8784.92,5472.8 h60
  text "12" at 6575.5,5352.8 h60
  text "Dielectric 4" at 6985.41,5352.8 h60
  text "FR-4 High TG" at 7925.15,5352.8 h60
  text "5.00mil" at 8784.92,5352.8 h60
  text "4.2" at 9434.76,5352.8 h60
  text "13" at 6575.5,5232.8 h60
  text "Signal Layer 5" at 6985.41,5232.8 h60
  text "Copper" at 7925.15,5232.8 h60
  text "2.80mil" at 8784.92,5232.8 h60
  text "14" at 6575.5,5112.8 h60
  text "Dielectric 6" at 6985.41,5112.8 h60
  text "FR-4 High TG" at 7925.15,5112.8 h60
  text "6.00mil" at 8784.92,5112.8 h60
  text "4.2" at 9434.76,5112.8 h60
  text "15" at 6575.5,4992.8 h60
  text "Signal Layer 6" at 6985.41,4992.8 h60
  text "Copper" at 7925.15,4992.8 h60
  text "2.80mil" at 8784.92,4992.8 h60
  text "16" at 6575.5,4872.8 h60
  text "Dielectric 7" at 6985.41,4872.8 h60
  text "FR-4 High TG" at 7925.15,4872.8 h60
  text "5.00mil" at 8784.92,4872.8 h60
  text "4.2" at 9434.76,4872.8 h60
  text "17" at 6575.5,4752.8 h60
  text "Bottom Layer" at 6985.41,4752.8 h60
  text "Copper" at 7925.15,4752.8 h60
  text "2.80mil" at 8784.92,4752.8 h60
  text "18" at 6575.5,4632.8 h60
  text "Bottom Solder" at 6985.41,4632.8 h60
  text "Solder Resist" at 7925.15,4632.8 h60
  text "0.50mil" at 8784.92,4632.8 h60
  text "3.3" at 9434.76,4632.8 h60
  text "19" at 6575.5,4512.8 h60
  text "Bottom Overlay" at 6985.41,4512.8 h60
  text ".Layer_Name" at 568,-1552.49 h60
M13 Component Bodies Top:
  text ".Layer_Name" at 577,-1558.49 h60
M14 Component Bodies Bottom:
  text ".Layer_Name" at 577,-1558.49 h60
M15 Courtyards Top:
  text ".Layer_Name" at 577,-1558.49 h60
M16 Courtyards Bottom:
  text ".Layer_Name" at 577,-1558.49 h60
Drill Drawing:
  circle w10: c4259.2,-344.43 r16.01
  circle w10: c4259.2,-344.43 r26.68
  lines w10: 4232.52,-224.36 4259.2,-251.04 4285.88,-224.36 4259.2,-197.68 4232.52,-224.36 ; 4232.52,-130.98 4285.88,-130.98 4285.88,-77.62 4232.52,-77.62 4232.52,-130.98 ; 4232.52,-10.92 4259.2,2.42 4285.88,-10.92 4272.54,15.76 4285.88,42.44 4259.2,29.1 4232.52,42.44 4245.86,15.76 4232.52,-10.92 ; 4232.52,122.48 4245.86,122.48 4245.86,109.14 4272.54,109.14 4272.54,122.48 4285.88,122.48 4285.88,149.16 4272.54,149.16 4272.54,162.5 4245.86,162.5 4245.86,149.16 4232.52,149.16 4232.52,122.48 ; 4232.52,229.2 4232.52,242.54 4245.86,255.88 4232.52,269.23 4232.52,282.57 4245.86,282.57 4259.2,269.23 4272.54,282.57 4285.88,282.57 4285.88,269.23 4272.54,255.88 4285.88,242.54 4285.88,229.2 4272.54,229.2 4259.2,242.54 4245.86,229.2 4232.52,229.2 ; 4232.52,349.27 4285.88,349.27 4285.88,402.63 4232.52,402.63 4232.52,349.27 ; 4232.52,482.67 4245.86,482.67 4259.2,469.33 4272.54,482.67 4285.88,482.67 4272.54,496.01 4285.88,509.35 4272.54,509.35 4259.2,522.69 4245.86,509.35 4232.52,509.35 4245.86,496.01 4232.52,482.67 ; 4232.52,642.75 4285.88,642.75 4259.2,589.39 4232.52,642.75 ; 4232.52,722.79 4245.86,722.79 4245.86,709.45 4272.54,709.45 4272.54,722.79 4285.88,722.79 4285.88,749.47 4272.54,749.47 4272.54,762.81 4245.86,762.81 4245.86,749.47 4232.52,749.47 4232.52,722.79 ; 4243.19,359.94 4275.2,359.94 4275.2,391.96 4243.19,391.96 4243.19,359.94 ; 4243.19,728.13 4251.19,728.13 4251.19,720.12 4267.2,720.12 4267.2,728.13 4275.2,728.13 4275.2,744.14 4267.2,744.14 4267.2,752.14 4251.19,752.14 4251.19,744.14 4243.19,744.14 4243.19,728.13
  lines w15: 4184.03,-407.12 10907.12,-407.12 ; 4184.03,793.5 10907.12,793.5 ; 4631.35,-527.19 4631.35,913.56 ; 5107.46,-527.19 5107.46,913.56 ; 6039.66,-527.19 6039.66,913.56 ; 6450.96,-527.19 6450.96,913.56 ; 7044.69,-527.19 7044.69,913.56 ; 8248.94,-527.19 8248.94,913.56 ; 8727.45,-527.19 8727.45,913.56 ; 9330.78,-527.19 9330.78,913.56 ; 4184.03,-527.19 10907.12,-527.19 10907.12,913.56 4184.03,913.56 4184.03,-527.19
  text "Symbol" at 4256.07,829.51 h57.63
  text "Count" at 4667.37,829.51 h57.63
  text "Hole Size" at 5143.48,829.51 h57.63
  text "Plated" at 6075.68,829.51 h57.63
  text "Hole Type" at 6486.98,829.51 h57.63
  text "Drill Layer Pair" at 7080.71,829.51 h57.63
  text "Via/Pad" at 8284.96,829.51 h57.63
  text "Pad Shape" at 8763.47,829.51 h57.63
  text "Template" at 9366.8,829.51 h57.63
  text "2" at 4667.37,709.45 h48.02
  text "50.00mil (1.270mm)" at 5143.48,709.45 h48.02
  text "PTH" at 6075.68,709.45 h48.02
  text "Round" at 6486.98,709.45 h48.02
  text "Top Layer - Bottom Layer" at 7080.71,709.45 h48.02
  text "Pad" at 8284.96,709.45 h48.02
  text "(Mixed)" at 8763.47,709.45 h48.02
  text "(Mixed)" at 9366.8,709.45 h48.02
  text "2" at 4667.37,589.39 h48.02
  text "254.00mil (6.452mm)" at 5143.48,589.39 h48.02
  text "PTH" at 6075.68,589.39 h48.02
  text "Round" at 6486.98,589.39 h48.02
  text "Top Layer - Bottom Layer" at 7080.71,589.39 h48.02
  text "Pad" at 8284.96,589.39 h48.02
  text "Rectangle" at 8763.47,589.39 h48.02
  text "r1727_1270h645o-229_0p2362_1905" at 9366.8,589.39 h48.02
  text "4" at 4667.37,469.33 h48.02
  text "39.37mil (1.000mm)" at 5143.48,469.33 h48.02
  text "PTH" at 6075.68,469.33 h48.02
  text "Round" at 6486.98,469.33 h48.02
  text "Top Layer - Bottom Layer" at 7080.71,469.33 h48.02
  text "Pad" at 8284.96,469.33 h48.02
  text "(Mixed)" at 8763.47,469.33 h48.02
  text "(Mixed)" at 9366.8,469.33 h48.02
  text "4" at 4667.37,349.27 h48.02
  text "51.18mil (1.300mm)" at 5143.48,349.27 h48.02
  text "PTH" at 6075.68,349.27 h48.02
  text "Round" at 6486.98,349.27 h48.02
  text "Top Layer - Bottom Layer" at 7080.71,349.27 h48.02
  text "Pad" at 8284.96,349.27 h48.02
  text "(Mixed)" at 8763.47,349.27 h48.02
  text "(Mixed)" at 9366.8,349.27 h48.02
  text "5" at 4667.37,229.2 h48.02
  text "7.87mil (0.200mm)" at 5143.48,229.2 h48.02
  text "PTH" at 6075.68,229.2 h48.02
  text "Round" at 6486.98,229.2 h48.02
  text "Top Layer - Bottom Layer" at 7080.71,229.2 h48.02
  text "Via" at 8284.96,229.2 h48.02
  text "Rounded" at 8763.47,229.2 h48.02
  text "v50h20" at 9366.8,229.2 h48.02
  text "24" at 4667.37,109.14 h48.02
  text "45.28mil (1.150mm)" at 5143.48,109.14 h48.02
  text "PTH" at 6075.68,109.14 h48.02
  text "Round" at 6486.98,109.14 h48.02
  text "Top Layer - Bottom Layer" at 7080.71,109.14 h48.02
  text "Pad" at 8284.96,109.14 h48.02
  text "(Mixed)" at 8763.47,109.14 h48.02
  text "(Mixed)" at 9366.8,109.14 h48.02
  text "26" at 4667.37,-10.92 h48.02
  text "40.00mil (1.016mm)" at 5143.48,-10.92 h48.02
  text "PTH" at 6075.68,-10.92 h48.02
  text "Round" at 6486.98,-10.92 h48.02
  text "Top Layer - Bottom Layer" at 7080.71,-10.92 h48.02
  text "Pad" at 8284.96,-10.92 h48.02
  text "(Mixed)" at 8763.47,-10.92 h48.02
  text "(Mixed)" at 9366.8,-10.92 h48.02
  text "37" at 4667.37,-130.98 h48.02
  text "63.00mil (1.600mm)" at 5143.48,-130.98 h48.02
  text "PTH" at 6075.68,-130.98 h48.02
  text "Round" at 6486.98,-130.98 h48.02
  text "Top Layer - Bottom Layer" at 7080.71,-130.98 h48.02
  text "Pad" at 8284.96,-130.98 h48.02
  text "Rounded" at 8763.47,-130.98 h48.02
  text "c221h160" at 9366.8,-130.98 h48.02
  text "116" at 4667.37,-251.04 h48.02
  text "16.00mil (0.406mm)" at 5143.48,-251.04 h48.02
  text "PTH" at 6075.68,-251.04 h48.02
  text "Round" at 6486.98,-251.04 h48.02
  text "Top Layer - Bottom Layer" at 7080.71,-251.04 h48.02
  text "Via" at 8284.96,-251.04 h48.02
  text "Rounded" at 8763.47,-251.04 h48.02
  text "v81h41" at 9366.8,-251.04 h48.02
  text "696" at 4667.37,-371.11 h48.02
  text "10.00mil (0.254mm)" at 5143.48,-371.11 h48.02
  text "PTH" at 6075.68,-371.11 h48.02
  text "Round" at 6486.98,-371.11 h48.02
  text "Top Layer - Bottom Layer" at 7080.71,-371.11 h48.02
  text "Via" at 8284.96,-371.11 h48.02
  text "Rounded" at 8763.47,-371.11 h48.02
  text "(Mixed)" at 9366.8,-371.11 h48.02
  text "916 Total" at 4667.37,-491.17 h48.02
  text ".Layer_Name" at 700,-700 h60
Mechanical 17:
  text ".Layer_Name" at 577,-1558.49 h60
Mechanical 18:
  text ".Layer_Name" at 577,-1558.49 h60
Mechanical 19:
  text ".Layer_Name" at 577,-1558.49 h60

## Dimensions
0,0 to 0,4000 on M2 Board Dimensions
0,0 to 4000,0 on M2 Board Dimensions
0,-1100 to 1000,-1100 on M2 Board Dimensions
